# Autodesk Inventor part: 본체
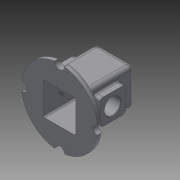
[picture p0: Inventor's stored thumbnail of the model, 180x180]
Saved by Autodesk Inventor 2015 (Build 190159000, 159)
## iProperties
Created: 2018-07
Part Number: 본체
Material: 일반
Document SubType Name: Modeling
Designer: pc
Density: 1 g/cm^3
Appearance: 기본값
Author: pc
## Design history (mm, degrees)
sketch "스케치1"
  geometry: A1 r 10 centre (75, 0) between (74.333, 9.978) and (74.333, -9.978); A2 r 10 centre (0, -75) between (9.978, -74.333) and (-9.978, -74.333); A3 r 10 centre (0, 75) between (-9.978, 74.333) and (9.978, 74.333); A4 r 10 centre (-75, 0) between (-74.333, -9.978) and (-74.333, 9.978); A5 r 75 centre (0, 0) between (9.978, -74.333) and (74.333, -9.978); A6 r 75 centre (0, 0) between (74.333, 9.978) and (9.978, 74.333); A7 r 75 centre (0, 0) between (-9.978, 74.333) and (-74.333, 9.978); A8 r 75 centre (0, 0) between (-74.333, -9.978) and (-9.978, -74.333); 5 further points
  constraints: 16 point on circle, 8 centre point, 5 coincident, 2 horizontal alignment, 2 vertical alignment
  dimensions: "d1" = 20 diameter of A1; "d2" = 20 diameter of A2; "d3" = 20 diameter of A3; "d4" = 20 diameter of A4; "d5" = 75 radius of A5; "d6" = 75 radius of A6; "d7" = 75 radius of A7; "d8" = 75 radius of A8; "d9" = 150 distance of point (75, 0) point (-75, 0); "d10" = 150 distance of point (0, 75) point (0, -75); "d11" = 75 distance of point (0, 0) point (75, 0); "d12" = 75 distance of point (0, -75) point (0, 0)
extrude "돌출1" new body sketch "스케치1" distance "d13" = 10; taper "d14" = 0 deg
sketch "스케치2"
  geometry: L1 (-37, -37)-(37, -37); L2 (37, -37)-(37, 37); L3 (37, 37)-(-37, 37); L4 (-37, 37)-(-37, -37); L5 (0, -37)-(0, 37); L6 (37, 0)-(-37, 0); 2 further points
  constraints: 12 end point, 5 midpoint, 2 parallel, 1 coincident, 1 horizontal, 1 perpendicular
  dimensions: "d15" = 74 distance of L3.end L2.end; "d16" = 74 distance of L2.end L1.end
extrude "돌출2" join sketch "스케치2" distance "d17" = 100; taper "d18" = 0 deg
sketch "스케치3"
  geometry: L1 (-20, -20)-(20, -20); L2 (20, -20)-(20, 20); L3 (20, 20)-(-20, 20); L4 (-20, 20)-(-20, -20); L5 (0, -20)-(0, 20); L6 (20, 0)-(-20, 0); 1 further point
  constraints: 12 end point, 4 midpoint, 2 parallel, 1 horizontal, 1 perpendicular
  dimensions: "d19" = 40 distance of L3.end L2.end; "d20" = 40 distance of L2.end L1.end; "d21" = 20 distance of L6.end point (0, 0); "d22" = 20 distance of L5.end point (0, 0)
extrude "돌출3" join sketch "스케치3" distance "d23" = 7; taper "d24" = 0 deg
sketch "스케치4"
  geometry: L1 (-32, 32)-(32, 32); L2 (32, 32)-(32, -32); L3 (32, -32)-(-32, -32); L4 (-32, -32)-(-32, 32); L5 (-32, 0)-(32, 0); L6 (0, -32)-(0, 32); 2 further points
  constraints: 12 end point, 5 midpoint, 2 parallel, 1 coincident, 1 horizontal, 1 perpendicular
  dimensions: "d25" = 64 distance of L2.end L3.end; "d26" = 64 distance of L1.end L2.end
extrude "돌출4" cut sketch "스케치4" distance "d27" = 105; taper "d28" = 0 deg
node "작업 평면1"
sketch "스케치5"
  geometry: L1 (0, 0)-(55, 0); L2 (30, -25)-(80, -25); L3 (80, -25)-(80, 25); L4 (80, 25)-(30, 25); L5 (30, 25)-(30, -25); L6 (30, -25)-(80, 25); L7 (80, -25)-(30, 25)
  constraints: 14 end point, 2 horizontal, 2 midpoint, 2 parallel, 1 perpendicular
  dimensions: "d32" = 55 distance of L1.start L1.end; "d33" = 50 distance of L4.end L3.end; "d34" = 50 distance of L3.end L2.end
extrude "돌출5" join sketch "스케치5" stored distance "d35" = 105; taper "d36" = 0 deg
sketch "스케치6"
  geometry: L1 (0, 0)-(0, 55); C1 r 16 at (0, 55)
  constraints: 2 end point, 1 centre point, 1 coincident, 1 vertical
  dimensions: "d37" = 55 distance of L1.start L1.end; "d38" = 32 diameter of C1
extrude "돌출6" cut sketch "스케치6" stored distance "d39" = 105; taper "d40" = 0 deg
sketch "스케치7"
  geometry: L1 (-25, -30)-(-25, 25); C1 r 16 at (-25, 25)
  constraints: 2 end point, 1 centre point, 1 coincident, 1 vertical
  dimensions: "d41" = 55 distance of L1.start L1.end; "d42" = 32 diameter of C1
extrude "돌출7" cut sketch "스케치7" distance "d43" = 105; taper "d44" = 0 deg
sketch "스케치8"
  geometry: C1 r 17.5 at (0, 0); 1 further point
  constraints: 1 centre point, 1 coincident
  dimensions: "d45" = 35 diameter of C1
extrude "돌출8" join sketch "스케치8" distance "d46" = 3; taper "d47" = 0 deg
sketch "스케치9"
  geometry: C1 r 14 at (0, 0); 1 further point
  constraints: 1 centre point, 1 coincident
  dimensions: "d48" = 28 diameter of C1
extrude "돌출9" cut sketch "스케치9" distance "d49" = 4; taper "d50" = 0 deg
sketch "스케치10"
  geometry: C1 r 10.5 at (0, 0); 1 further point
  constraints: 1 centre point, 1 coincident
  dimensions: "d51" = 21 diameter of C1
extrude "돌출10" cut sketch "스케치10" stored distance "d52" = 4; taper "d53" = 0 deg
fillet "모깎기1" dims "d54" = 8
fillet "모깎기2" dims "d55" = 6
chamfer "모따기1" distance "d56" = 1; stored, may be unused: second distance "d57" = 2, angle "d58" = 45 deg
fillet "모깎기3" dims "d59" = 3
fillet "모깎기4" dims "d60" = 3
fillet "모깎기5" dims "d61" = 3
sketch "스케치11"
  geometry: A1 r 9 centre (-44, 38) between (-44, 47) and (-53, 38) reference; A2 r 9 centre (-6, 38) between (3, 38) and (-6, 47) reference; A3 r 9 centre (-6, 0) between (-6, -9) and (3, 0) reference; A4 r 9 centre (-44, 0) between (-53, 0) and (-44, -9) reference; 5 further points
  constraints: 4 coincident, 1 horizontal alignment
hole "구멍1" sketch "스케치11" at (-44, 38), (-6, 38), (-6, 0), (-44, 0) diameter "d62" = 3.242; stored, may be unused: countersink angle "d66" = 90 deg, drill point angle "d68" = 118 deg; dims "d63" = 8, "d64" = 4, "d65" = 2, "d67" = 10
fillet "모깎기6" dims "d69" = 3
sketch "스케치12"
  geometry: L1 (32, 55)-(25, 55); L2 (32, 80)-(25, 80); L3 (32, 80)-(25, 77.452); L4 (25, 77.452)-(25, 55); L5 (32, 80)-(32, 55); 1 further point
  constraints: 10 end point, 1 parallel
  dimensions: "d70" = 25 distance between parallel lines of L1 L2; "d82" = 7 horizontal distance of L2.start L3.end; "d85" = 22.45221 distance of L3.end L1.end; "d86" = 25 distance of L2.start L1.start; "d87" = 7 distance of L1.start L1.end; "d88" = 2.54779 distance of L3.end L2.end; "d89" = 80 distance from line of point (0, 0) L2; "d90" = 25 horizontal distance of point (0, 0) L1.end; "d91" = 55 vertical distance of L1.start point (0, 0)
revolve "회전1" sketch "스케치12" stored, may be unused: angle "d84" = 90 deg
sketch "스케치13"
  geometry: C1 r 25 at (0, 0) reference; C2 r 22.452 at (0, 0) reference; C3 r 16 at (0, 0); 1 further point
  constraints: 1 centre point, 1 coincident
  dimensions: "d92" = 32 diameter of C3
extrude "돌출11" cut sketch "스케치13" stored distance "d93" = 4; taper "d94" = 0 deg
node "작업 평면2"
sketch "스케치14"
  geometry: L1 (0, -9.978)-(0, 9.978) reference; L2 (-120, 17.5)-(-120, -17.5) reference; 3 further points
  constraints: 1 horizontal alignment, 1 midpoint, 1 other
  dimensions: "d96" = 30 distance from line of point (-90, 0) L2
feature "엠보싱1" sketch "스케치14" dims "d15" = 74, "d16" = 74, "d97" = 0.5, "d98" = 0
node "솔리드1"
mirror "대칭1"
mirror "대칭2"
mirror "대칭3"
node "투영된 루프1"
other parameters: "d95" = -37
